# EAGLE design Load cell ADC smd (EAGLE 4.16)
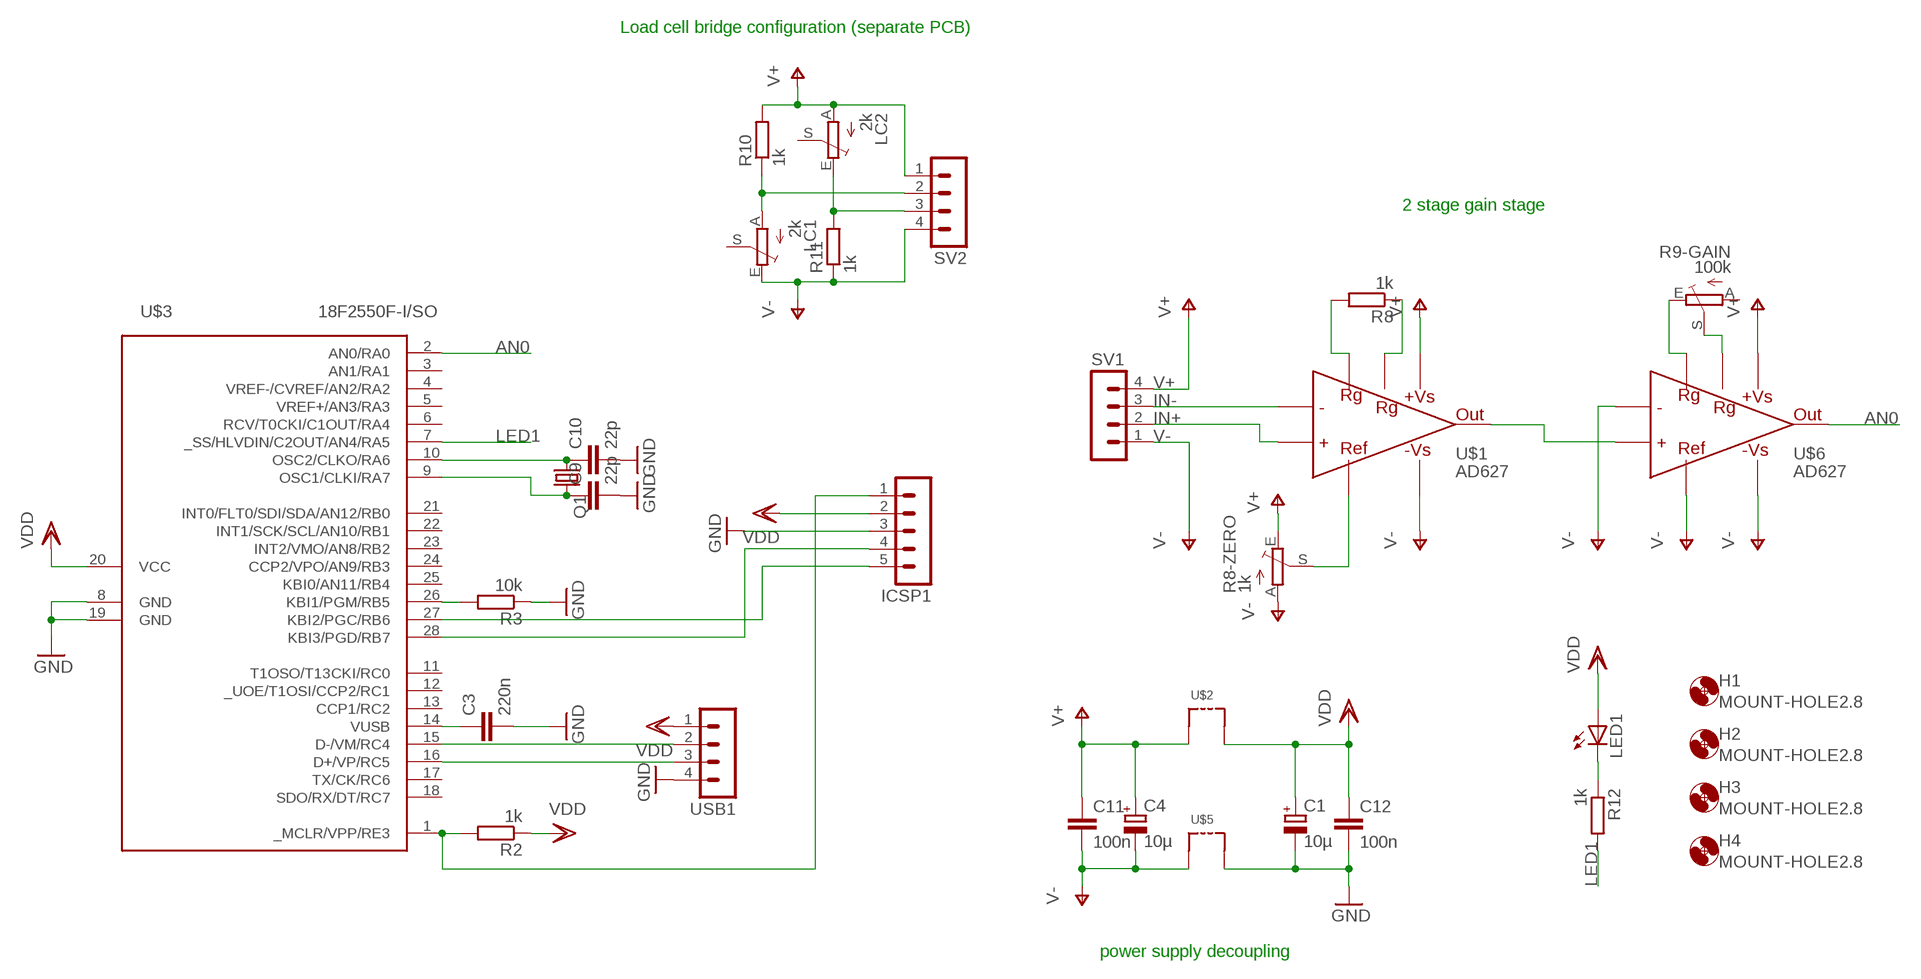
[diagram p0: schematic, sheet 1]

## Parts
C1  10µ  CPOL-EUSMCB  [SMC_B]
C3  220n  C-EUC1206  [C1206]
C4  10µ  CPOL-EUSMCB  [SMC_B]
C9  22p  C-EUC1206  [C1206]
C10  22p  C-EUC1206  [C1206]
C11  100n  C-EUC1206  [C1206]
C12  100n  C-EUC1206  [C1206]
H1  MOUNT-HOLE2.8  [2,8]
H2  MOUNT-HOLE2.8  [2,8]
H3  MOUNT-HOLE2.8  [2,8]
H4  MOUNT-HOLE2.8  [2,8]
ICSP1  MA05-1  [MA05-1]
LC1  2k  TRIM_EU-B90P  [SP19L]
LC2  2k  TRIM_EU-B90P  [SP19L]
LED1  LEDCHIPLED_1206  [CHIPLED_1206]
Q1  CRYSTALHC49UP  [HC49UP]
R2  1k  R-EU_M1206  [M1206]
R3  10k  R-EU_M1206  [M1206]
R8  1k  R-EU_M1206  [M1206]
R8-ZERO  1k  TRIM_EU-B90P  [SP19L]
R9-GAIN  100k  TRIM_EU-B90P  [SP19L]
R10  1k  R-EU_0207/7  [0207/7]
R11  1k  R-EU_0207/7  [0207/7]
R12  1k  R-EU_M1206  [M1206]
SV1  MA04-1  [MA04-1]
SV2  MA04-1  [MA04-1]
U$1  AD627  [AD627]
U$2  GROUNDBRIDGE_BOTTOM  [GROUNDBRIDGE_BOTTOM]
U$3  18F2550F-I/SO  [SO-28W]
U$5  GROUNDBRIDGE  [GROUNDBRIDGE]
U$6  AD627  [AD627]
USB1  MA04-1  [MA04-1]

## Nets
AN0: U$3.2(AN0/RA0) U$6.P$6
GND: C1.- C3.2 C9.2 C10.2 C12.2 ICSP1.3 R3.1 U$3.8(GND) U$3.19(GND) U$5.P$4 USB1.4
IN+: SV1.2 U$1.P$3
IN-: SV1.3 U$1.P$2
LED1: R12.2 U$3.7(_SS/HLVDIN/C2OUT/AN4/RA5)
N$2: C9.1 Q1.2 U$3.9(OSC1/CLKI/RA7)
N$3: C10.1 Q1.1 U$3.10(OSC2/CLKO/RA6)
N$4: R8.2 U$1.P$1
N$5: R8.1 U$1.P$8
N$6: LED1.C R12.1
N$8: R9-GAIN.S U$6.P$8
N$10: U$1.P$6 U$6.P$3
N$11: R9-GAIN.E U$6.P$1
N$15: R8-ZERO.S U$1.P$5
N$18: ICSP1.1 R2.2 U$3.1(_MCLR/VPP/RE3)
N$19: C3.1 U$3.14(VUSB)
N$20: R3.2 U$3.26(KBI1/PGM/RB5)
N$21: U$3.16(D+/VP/RC5) USB1.3
N$22: U$3.15(D-/VM/RC4) USB1.2
N$23: ICSP1.4 U$3.28(KBI3/PGD/RB7)
N$24: LC2.E R11.2 SV2.3
N$25: LC1.A R10.1 SV2.2
N$26: ICSP1.5 U$3.27(KBI2/PGC/RB6)
V+: C4.+ C11.1 LC2.A R8-ZERO.E R10.2 SV1.4 SV2.1 U$1.P$7 U$2.P$3 U$6.P$7
V-: C4.- C11.2 LC1.E R8-ZERO.A R11.1 SV1.1 SV2.4 U$1.P$4 U$5.P$3 U$6.P$2 U$6.P$4 U$6.P$5
VDD: C1.+ C12.1 ICSP1.2 LED1.A R2.1 U$2.P$4 U$3.20(VCC) USB1.1
Unconnected: LC1.S LC2.S R9-GAIN.A U$3.3(AN1/RA1) U$3.4(VREF-/CVREF/AN2/RA2) U$3.5(VREF+/AN3/RA3) U$3.6(RCV/T0CKI/C1OUT/RA4) U$3.11(T1OSO/T13CKI/RC0) U$3.12(_UOE/T1OSI/CCP2/RC1) U$3.13(CCP1/RC2) U$3.17(TX/CK/RC6) U$3.18(SDO/RX/DT/RC7) U$3.21(INT0/FLT0/SDI/SDA/AN12/RB0) U$3.22(INT1/SCK/SCL/AN10/RB1) U$3.23(INT2/VMO/AN8/RB2) U$3.24(CCP2/VPO/AN9/RB3) U$3.25(KBI0/AN11/RB4)

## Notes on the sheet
- Load cell bridge configuration (separate PCB)
- 2 stage gain stage
- power supply decoupling

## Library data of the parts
C1 C4 = rcl:CPOL-EU: POLARIZED CAPACITOR, European symbol
C3 C9-C12 = rcl:C-EU: CAPACITOR, European symbol
H1-H4 = holes:MOUNT-HOLE: MOUNTING HOLE with drill center marker
ICSP1 = con-lstb:MA05-1: PIN HEADER
LC1 LC2 R8-ZERO R9-GAIN = pot:TRIM_EU-: POTENTIOMETER
LED1 = led:LED: LED
Q1 = crystal:CRYSTAL: CRYSTAL
R2 R3 R8 R10-R12 = rcl:R-EU_: RESISTOR, European symbol
SV1 SV2 USB1 = con-lstb:MA04-1: PIN HEADER
U$1 U$6 = David Steeman:AD627
U$2 = David Steeman:GROUNDBRIDGE_BOTTOM
U$3 = redpic-microchip-pic:18F2550: Microchip PIC 18F2550 with FS-USB
U$5 = David Steeman:GROUNDBRIDGE: Ground bridge top layer

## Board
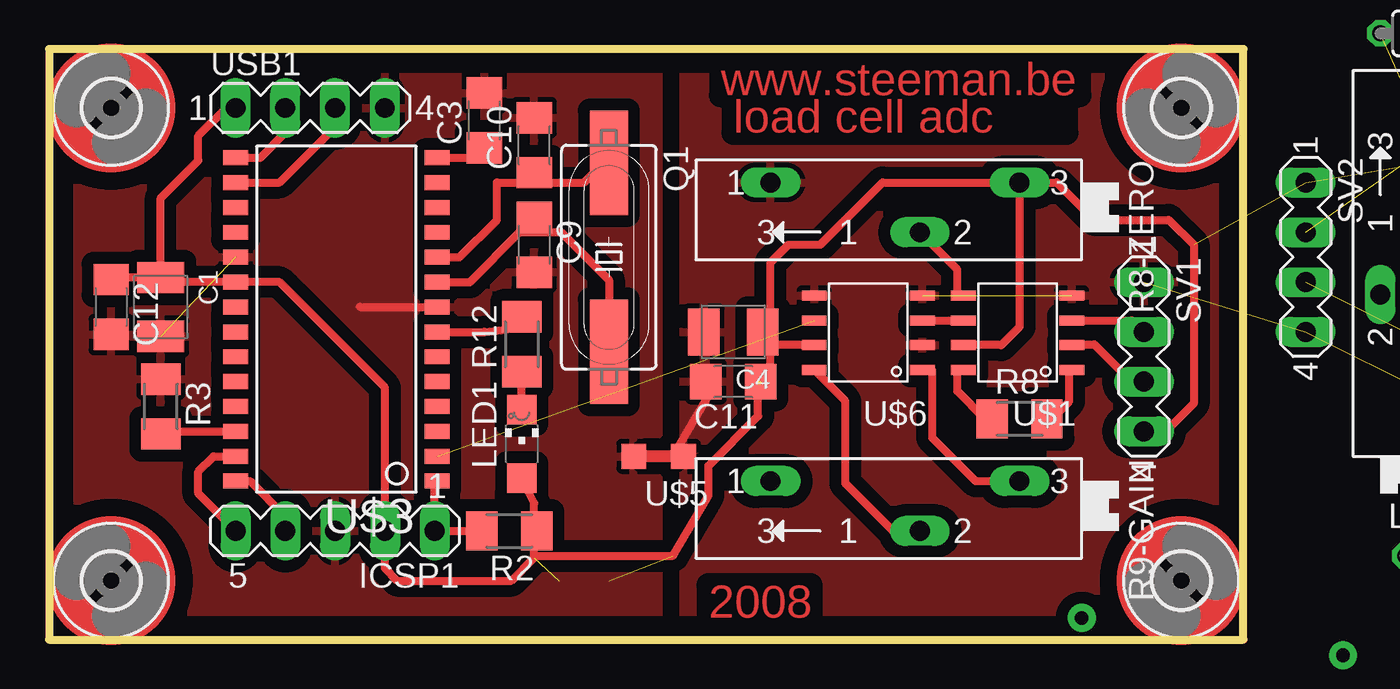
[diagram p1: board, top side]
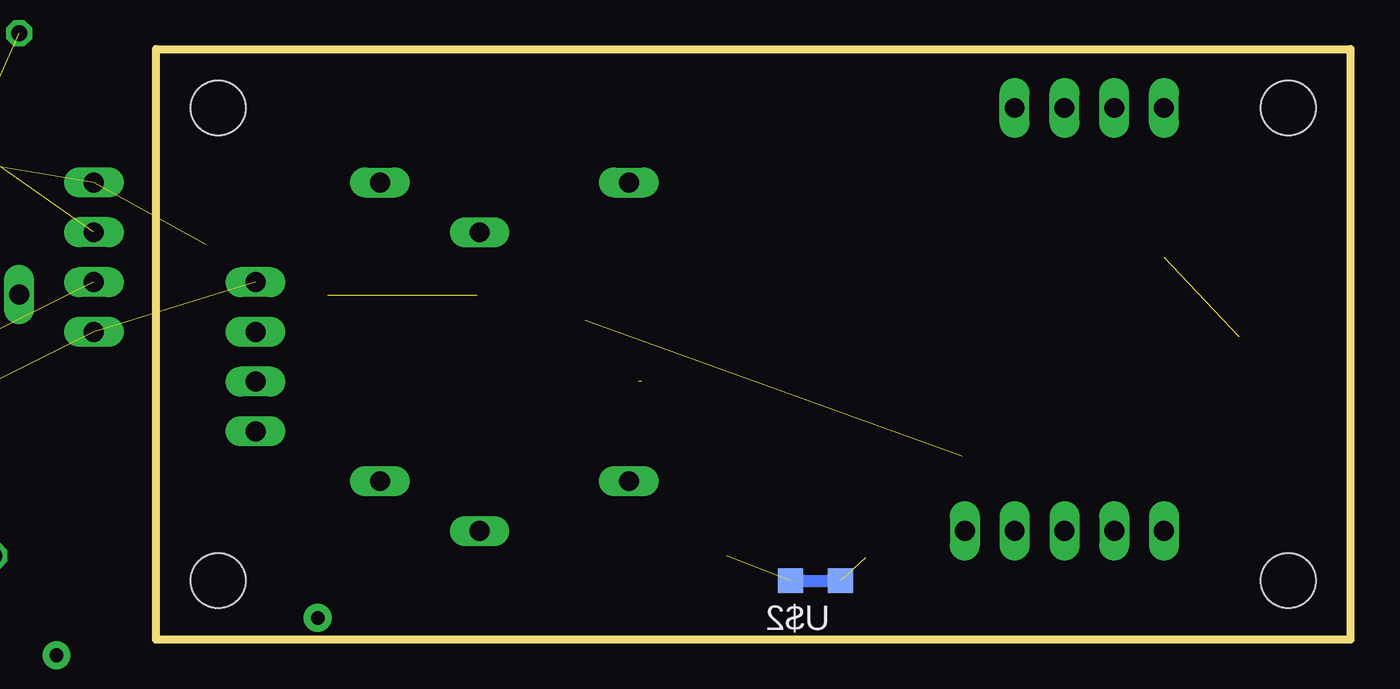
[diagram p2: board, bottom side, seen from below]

Size 60.95 x 30.15 mm. Coordinates in mm from the lower left corner, seen from the top.
Outline: 60.95,0 60.95,30.15 0,30.15 0,0 60.95,0
Copper layers (1*16): Top 0.035mm / dielectric 1.5mm / Bottom 0.035mm
Design rules "default": minimum track width 10mil, minimum drill 24mil, track to track 8mil, track to pad 8mil, pad to pad 8mil, via to via 8mil, smd to smd 8mil, copper to edge 40mil, drill to drill 8mil, minimum pad ring 10mil, minimum via ring 8mil, stop-mask expansion 4mil, vias tented up to drill 0mil, thermal gap 10mil

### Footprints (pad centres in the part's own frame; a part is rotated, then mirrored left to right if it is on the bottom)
SMC_B = smd 1.6 x 2.4: + -1.5,0; - 1.5,0
C1206 = smd 1.6 x 1.8: 1 -1.4,0; 2 1.4,0
2,8 = hole 2.8: 0,0
MA05-1 = drill 1.016 long: 1 -5.08,0; 2 -2.54,0; 3 0,0; 4 2.54,0; 5 5.08,0
SP19L = drill 1.016 long: A 5.715,-1.27; E -6.985,-1.27; S -1.905,1.27
CHIPLED_1206 = smd 1.5 x 1.5: A 0,-1.75; C 0,1.75
HC49UP = smd 5.334 x 1.93: 1 -4.826,0; 2 4.826,0
M1206 = smd 1.6 x 2: 1 -1.4,0; 2 1.4,0
0207/7 = drill 0.813 octagon: 1 -3.81,0; 2 3.81,0
MA04-1 = drill 1.016 long: 1 -3.81,0; 2 -1.27,0; 3 1.27,0; 4 3.81,0
AD627 = smd 0.51 x 1.27: P$1 -1.95,-2.03; P$2 -0.68,-2.03; P$3 0.59,-2.03; P$4 1.86,-2.03; P$5 1.86,3.49; P$6 0.59,3.49; P$7 -0.68,3.49; P$8 -1.95,3.49
GROUNDBRIDGE_BOTTOM = smd 1.27 x 1.27 bottom: P$3 -1.27,0; P$4 1.27,0
SO-28W = smd 0.762 x 1.27: 1 -7.62,-5.207; 2 -6.35,-5.207; 3 -5.08,-5.207; 4 -3.81,-5.207; 5 -2.54,-5.207; 6 -1.27,-5.207; 7 0,-5.207; 8 1.27,-5.207; 9 2.54,-5.207; 10 3.81,-5.207; 11 5.08,-5.207; 12 6.35,-5.207; 13 7.62,-5.207; 14 8.89,-5.207; 15 8.89,5.08; 16 7.62,5.08; 17 6.35,5.08; 18 5.08,5.08; 19 3.81,5.08; 20 2.54,5.08; 21 1.27,5.08; 22 0,5.08; 23 -1.27,5.08; 24 -2.54,5.08; 25 -3.81,5.08; 26 -5.08,5.08; 27 -6.35,5.08; 28 -7.62,5.08
GROUNDBRIDGE = smd 1.27 x 1.27: P$3 -1.27,0; P$4 1.27,0

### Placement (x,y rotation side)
C1  5.71,16.98 270 top
C3  22.22,26.5 90 top
C4  34.92,15.71 180 top
C9  24.76,20.15 270 top
C10  24.76,25.23 90 top
C11  34.92,13.17 180 top
C12  3.17,16.98 270 top
H1  3.17,27.14 90 top
H2  57.78,3.01 0 top
H3  57.78,27.14 0 top
H4  3.17,3.01 90 top
ICSP1  14.6,5.55 180 top
LC1  not placed on the board
LC2  not placed on the board
LED1  24.12,10 0 top
Q1  28.57,19.52 270 top
R2  23.49,5.55 180 top
R3  5.71,11.9 270 top
R8  49.53,11.27 0 top
R8-ZERO  42.54,22.06 180 top
R9-GAIN  42.54,6.82 180 top
R10  not placed on the board
R11  not placed on the board
R12  24.12,15.08 90 top
SV1  55.88,14.44 270 top
SV2  not placed on the board
U$1  50.16,15.71 90 top
U$2  27.3,3.01 180 top
U$3  14.6,15.71 90 top
U$5  31.11,9.36 180 top
U$6  42.54,15.71 90 top
USB1  13.33,27.14 0 top

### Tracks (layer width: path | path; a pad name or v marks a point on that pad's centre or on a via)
AN0  (1 unrouted)
GND  (1 unrouted)
  Top 0.406: 15.87,16.98 U$3.8
  pour Top (isolate 0.61): -0.64,30.95 31.11,30.95 31.11,-0.8 -0.64,-0.8
IN+
  Top 0.406: U$1.P$3 55.24,16.3 SV1.2
IN-
  Top 0.406: SV1.3 55.24,13.17 53.34,15.08 52.07,15.08 52.07,15.03 U$1.P$2
LED1
  Top 0.406: R12.2 23.36,15.84 22.22,15.71 U$3.7
N$1  (via drill 0.7 pad 1.42)
  other vias: 66.03,-0.8
N$2
  Top 0.406: 24.76,20.79 26.14,20.79 28.57,18.36 Q1.2 | 24.76,20.79 C9.1 | U$3.9 21.48,18.25 24.02,20.79 24.76,20.79
N$3
  Top 0.406: 24.76,23.33 27.3,23.33 28.57,24.6 Q1.1 | U$3.10 20.95,19.52 22.86,21.42 22.86,23.33 24.76,23.33 | 24.76,23.33 C10.1
N$4
  Top 0.406: 52.07,13.76 52.07,13.81 | 52.07,13.76 U$1.P$1 | R8.2 51.17,11.27 52.07,12.16 52.07,13.76
N$5
  Top 0.406: 46.35,13.76 46.35,13.81 | 46.35,13.76 U$1.P$8 | R8.1 47.77,11.27 46.35,12.69 46.35,13.76
N$6
  Top 0.406: LED1.C R12.1
N$7  (via drill 0.7 pad 1.42)
  other vias: 52.7,1.1
N$8
  Top 0.406: U$6.P$8 40.64,12.18 40.64,7.98 43.07,5.55 R9-GAIN.S
N$10
  Top 0.406: 46.35,16.3 U$1.P$6 | U$6.P$3 46.35,16.3 | 46.35,16.3 46.35,16.34
N$11
  Top 0.406: U$6.P$1 45.08,13.76 45.08,10.29 47.29,8.09 R9-GAIN.E
N$15
  Top 0.406: U$1.P$5 46.35,17.57 46.35,18.88 R8-ZERO.S
N$18
  Top 0.406: 22.22,4.92 R2.2 ICSP1.1 19.68,8.09 U$3.1
N$19
  Top 0.406: 19.68,24.6 U$3.14 22.22,24.6 C3.1
N$20
  Top 0.406: R3.2 6.34,10.63 U$3.26
N$21
  Top 0.406: U$3.16 11.76,23.33 14.6,26.17 USB1.3
N$22
  Top 0.406: U$3.15 10.79,24.6 12.06,25.87 USB1.2
N$23
  Top 0.406: U$3.28 10.26,8.09 12.06,6.29 ICSP1.4
N$24  (2 unrouted)
N$25  (2 unrouted)
N$26
  Top 0.406: ICSP1.5 7.62,7.46 7.62,8.58 8.4,9.36 U$3.27
V+  (5 unrouted)
  Top 0.406: C4.+ 36.83,15.71 36.83,15.08 | U$6.P$7 38.73,15.03 38.73,15.08 36.83,15.08 | U$1.P$7 48.6,15.03 49.53,15.96 R8-ZERO.E | R8-ZERO.E 51.43,23.33 53.34,21.42 57.15,21.42 58.41,20.15 58.41,12.05 57,10.63 SV1.4 | 36.83,15.08 36.83,19.26 37.72,20.15 39.37,20.15 42.54,23.33 R8-ZERO.E | C11.1 36.83,13.17 36.83,15.08 | 36.19,13.17 36.19,11.42 33.65,8.88 33.65,7.35 31.85,4.28 24.76,4.28
V-  (4 unrouted)
  Top 0.406: C11.2 33.65,13.17 33.65,12.43 31.85,9.36 U$5.P$3
  pour Top (isolate 0.61): 32.38,30.95 61.59,30.95 61.59,-0.8 32.38,-0.8
VDD  (1 unrouted)
  Top 0.406: C1.+ 3.17,18.48 C12.1 | 24.76,4.92 24.76,4.17 23.6,3.01 17.77,3.01 17.14,3.64 ICSP1.2 17.14,12.87 11.76,18.25 U$3.20 5.71,18.25 C1.+ | 24.76,4.92 R2.1 | LED1.A 24.76,6.97 24.76,4.92 | USB1.1 9.04,27.14 7.62,25.72 7.62,24.45 5.71,22.54 C1.+
(copper drawn outside any net)
  shapes: Top circle x4

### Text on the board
Top: www.steeman.be | load cell adc | 2008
